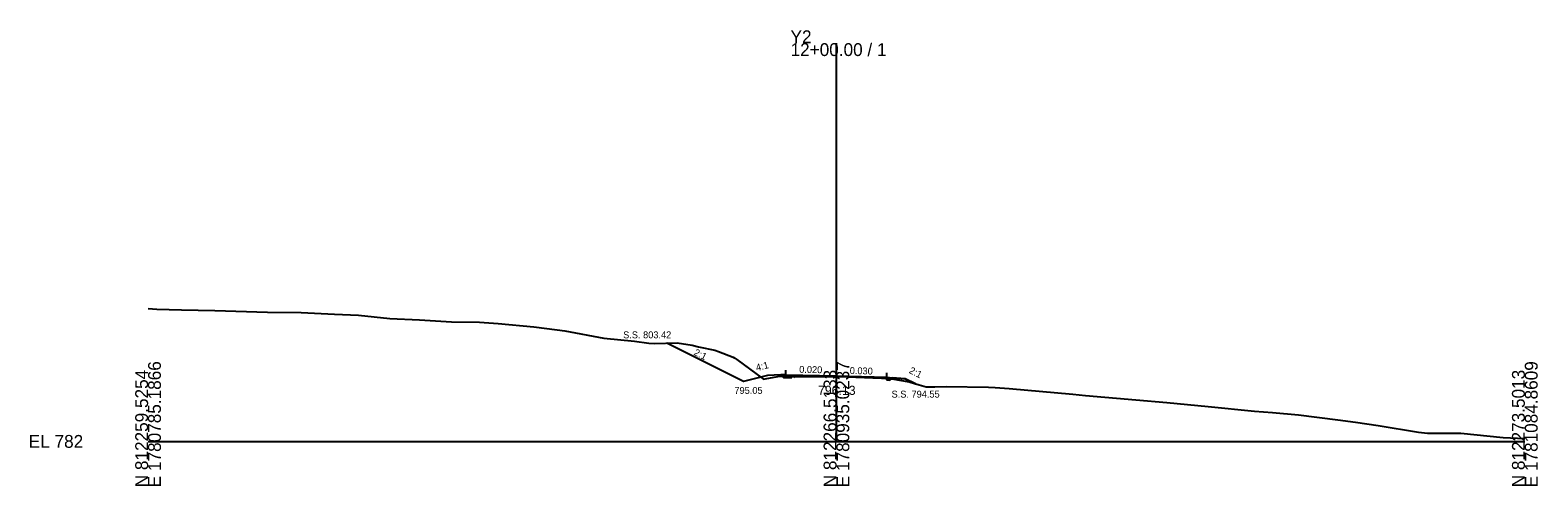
# Model space of a CAD drawing. Extents: x -26 to 303, y -10 to 3096.
# Drawn here: x -25.7 to 302.8, y 2490.3 to 2589.7 of the extents above; entities that cross this region are included whole.
import ezdxf

# ---------------------------------------------------------------- set-up
doc = ezdxf.new("R2010")
doc.units = 0
for name, color, linetype in [('Exist Cross Section Cell', 7, 'Continuous'), ('Exist XS Center Line Elevation Label', 7, 'Continuous'), ('Exist XS Ground Line', 7, 'Continuous'), ('Prop XS Ditch Slope Text', 7, 'Continuous'), ('Prop XS Ditch Standard Text', 7, 'Continuous'), ('Prop XS Dump Level', 7, 'Continuous'), ('Prop XS Earthwork Shape', 7, 'Continuous'), ('Prop XS EOT Tick Mark', 7, 'Continuous'), ('Prop XS Finish Grade', 7, 'Continuous'), ('Prop XS Finish Grade Earthwork', 7, 'Continuous'), ('Prop XS Finish Grade Pavement', 7, 'Continuous'), ('Prop XS Pvmt Edge Slope', 7, 'Continuous'), ('Prop XS SE Text', 7, 'Continuous'), ('Prop XS Side Slope Text', 7, 'Continuous'), ('Prop XS SS Elevation Text', 7, 'Continuous'), ('Prop XS Subgrade Earthwork', 7, 'Continuous')]:
    doc.layers.add(name, color=color, linetype=linetype)

msp = doc.modelspace()

# ---------------------------------------------------------------- linework, layer by layer
at = {"layer": 'Exist Cross Section Cell'}
for p, q in [((150, 2500), (150, 2586.81)), ((0, 2500), (150, 2500)), ((150, 2500), (300, 2500))]:
    msp.add_line(p, q, dxfattribs=at)
at = {"layer": 'Exist XS Ground Line'}
for p, q in [((0, 2528.94), (1.88, 2528.85)), ((1.88, 2528.85), (7.26, 2528.67)), ((7.26, 2528.67), (14.58, 2528.51)), ((14.58, 2528.51), (26.04, 2528.19)), ((26.04, 2528.19), (33.38, 2528.1)), ((33.38, 2528.1), (40.63, 2527.73)), ((40.63, 2527.73), (45.85, 2527.52)), ((45.85, 2527.52), (52.68, 2526.77)), ((52.68, 2526.77), (59.12, 2526.49)), ((59.12, 2526.49), (66.1, 2526.1)), ((66.1, 2526.1), (72.19, 2526.01)), ((72.19, 2526.01), (76.29, 2525.68)), ((76.29, 2525.68), (84.03, 2525)), ((84.03, 2525), (86.87, 2524.6)), ((86.87, 2524.6), (90.81, 2524.1)), ((90.81, 2524.1), (99.31, 2522.48)), ((99.31, 2522.48), (105.98, 2521.87)), ((105.98, 2521.87), (109.15, 2521.43)), ((109.15, 2521.43), (110.25, 2521.33)), ((110.25, 2521.33), (115.31, 2521.49)), ((115.31, 2521.49), (118.54, 2520.97)), ((118.54, 2520.97), (119.92, 2520.61)), ((119.92, 2520.61), (123.48, 2519.89)), ((123.48, 2519.89), (124.32, 2519.63)), ((124.32, 2519.63), (127.53, 2518.34)), ((127.53, 2518.34), (127.87, 2518.12)), ((127.87, 2518.12), (128.28, 2517.82)), ((128.28, 2517.82), (134.14, 2513.56)), ((134.14, 2513.56), (134.83, 2513.7)), ((134.83, 2513.7), (137.63, 2514.23)), ((137.63, 2514.23), (139.6, 2514.19)), ((139.6, 2514.19), (140.3, 2514.16)), ((140.3, 2514.16), (141.47, 2514.15)), ((141.47, 2514.15), (150, 2514.13)), ((150, 2514.13), (150.49, 2514.13)), ((150.49, 2514.13), (159.85, 2513.81)), ((159.85, 2513.81), (161.22, 2513.76)), ((161.22, 2513.76), (162.05, 2513.63)), ((162.05, 2513.63), (165.83, 2512.95)), ((165.83, 2512.95), (168.01, 2512.32)), ((168.01, 2512.32), (169.54, 2511.89)), ((169.54, 2511.89), (171.43, 2511.87)), ((171.43, 2511.87), (173.91, 2511.98)), ((173.91, 2511.98), (183.14, 2511.79)), ((183.14, 2511.79), (184.58, 2511.77)), ((184.58, 2511.77), (187.65, 2511.52)), ((187.65, 2511.52), (201.53, 2510.27)), ((201.53, 2510.27), (204.29, 2510.03)), ((204.29, 2510.03), (215.27, 2509.04)), ((215.27, 2509.04), (222.02, 2508.5)), ((222.02, 2508.5), (231.01, 2507.58)), ((231.01, 2507.58), (241.1, 2506.6)), ((241.1, 2506.6), (244.99, 2506.28)), ((244.99, 2506.28), (250.71, 2505.78)), ((250.71, 2505.78), (259.25, 2504.71)), ((259.25, 2504.71), (263.09, 2504.19)), ((263.09, 2504.19), (268.08, 2503.46)), ((268.08, 2503.46), (276.8, 2502.02)), ((276.8, 2502.02), (278.83, 2501.77)), ((278.83, 2501.77), (279.35, 2501.79)), ((279.35, 2501.79), (280.98, 2501.78)), ((280.98, 2501.78), (282.42, 2501.77)), ((282.42, 2501.77), (286.06, 2501.81)), ((286.06, 2501.81), (295.29, 2500.87)), ((295.29, 2500.87), (300, 2500.6))]:
    msp.add_line(p, q, dxfattribs=at)
at = {"layer": 'Prop XS Dump Level'}
for p, q in [((139, 2514.52), (150, 2514.3)), ((150, 2514.3), (161, 2513.97))]:
    msp.add_line(p, q, dxfattribs=at)
at = {"layer": 'Prop XS Earthwork Shape'}
for points in [[(113.02, 2521.42), (115.31, 2521.49), (118.54, 2520.97), (119.92, 2520.61), (123.48, 2519.89), (124.32, 2519.63), (127.53, 2518.34), (127.87, 2518.12), (128.28, 2517.82), (133.54, 2514), (129.76, 2513.05)], [(135, 2514.36), (133.54, 2514), (134.14, 2513.56), (134.83, 2513.7), (137.63, 2514.23), (138.16, 2514.22), (137.9, 2514.48)], [(140.3, 2513.91), (140.3, 2514.16), (139.6, 2514.19), (138.16, 2514.22), (138.43, 2513.95)], [(161, 2513.77), (161.22, 2513.76), (161.89, 2513.65), (161.6, 2513.37), (161, 2513.39)], [(161.89, 2513.65), (162.05, 2513.63), (165.83, 2512.95), (167.21, 2512.55), (165, 2513.65), (162.11, 2513.88)]]:
    msp.add_lwpolyline(points, close=True, dxfattribs=at)
at = {"layer": 'Prop XS EOT Tick Mark'}
for p, q in [((139, 2514.52), (139, 2515.52)), ((161, 2513.97), (161, 2514.97))]:
    msp.add_line(p, q, dxfattribs=at)
at = {"layer": 'Prop XS Finish Grade'}
for p, q in [((139, 2514.52), (137.9, 2514.48)), ((161, 2513.97), (162.11, 2513.88))]:
    msp.add_line(p, q, dxfattribs=at)
at = {"layer": 'Prop XS Finish Grade Earthwork'}
for p, q in [((129.76, 2513.05), (113.02, 2521.42)), ((135, 2514.36), (129.76, 2513.05)), ((137.9, 2514.48), (135, 2514.36)), ((162.11, 2513.88), (165, 2513.65)), ((165, 2513.65), (167.21, 2512.55))]:
    msp.add_line(p, q, dxfattribs=at)
at = {"layer": 'Prop XS Finish Grade Pavement'}
for p, q in [((139, 2514.52), (150, 2514.3)), ((150, 2514.3), (161, 2513.97))]:
    msp.add_line(p, q, dxfattribs=at)
at = {"layer": 'Prop XS Pvmt Edge Slope'}
for p, q in [((139, 2514.52), (138.43, 2513.95)), ((161, 2513.97), (161.6, 2513.37))]:
    msp.add_line(p, q, dxfattribs=at)
at = {"layer": 'Prop XS Subgrade Earthwork'}
for p, q in [((138.43, 2513.95), (137.9, 2514.48)), ((138.43, 2513.95), (140.3, 2513.91)), ((140.3, 2513.91), (140.3, 2514.16)), ((161, 2513.39), (161, 2513.77)), ((161, 2513.39), (161.6, 2513.37)), ((161.6, 2513.37), (162.11, 2513.88))]:
    msp.add_line(p, q, dxfattribs=at)

# ---------------------------------------------------------------- texts
at = {"layer": 'Exist Cross Section Cell'}
for s, p in [('Y2', (140, 2586.81)), ('12+00.00 / 1', (140, 2584.01)), ('EL 782', (-26, 2498.6))]:
    msp.add_text(s, height=2.8, dxfattribs=at).set_placement(p)
for s, p in [('E 1780785.1866', (2.8, 2490)), ('E 1780935.0237', (152.8, 2490)), ('E 1781084.8609', (302.8, 2490)), ('N 812259.5254', (0, 2490)), ('N 812266.5133', (150, 2490)), ('N 812273.5013', (300, 2490))]:
    msp.add_text(s, height=2.8, rotation=90, dxfattribs=at).set_placement(p)
at = {"layer": 'Exist XS Center Line Elevation Label'}
msp.add_text('796.13', height=2, dxfattribs=at).set_placement((145.99, 2510.13))
at = {"layer": 'Prop XS Ditch Slope Text'}
msp.add_text('4:1', height=1.5, rotation=14.0362, dxfattribs=at).set_placement((132.64, 2515.32))
at = {"layer": 'Prop XS Ditch Standard Text'}
msp.add_text('795.05', height=1.5, dxfattribs=at).set_placement((127.77, 2510.36))
at = {"layer": 'Prop XS Dump Level'}
for s, height, p in [('Case1', 0.04, (135, 2514.32)), ('Eop', 0.3, (140.3, 2513.86)), ('Eop', 0.3, (161.22, 2513.46)), ('Case1', 0.04, (165, 2513.61))]:
    msp.add_text(s, height=height, dxfattribs=at).set_placement(p)
at = {"layer": 'Prop XS SE Text'}
for s, rotation, p in [('0.020', 358.8542, (141.88, 2514.96)), ('0.030', 358.2816, (152.88, 2514.71))]:
    msp.add_text(s, height=1.5, rotation=rotation, dxfattribs=at).set_placement(p)
at = {"layer": 'Prop XS Side Slope Text'}
for p in [(118.79, 2518.92), (165.69, 2514.98)]:
    msp.add_text('2:1', height=1.5, rotation=333.4349, dxfattribs=at).set_placement(p)
at = {"layer": 'Prop XS SS Elevation Text'}
for s, p in [('S.S. 803.42', (103.52, 2522.48)), ('S.S. 794.55', (162.01, 2509.55))]:
    msp.add_text(s, height=1.5, dxfattribs=at).set_placement(p)

doc.saveas('drawing.dxf')
